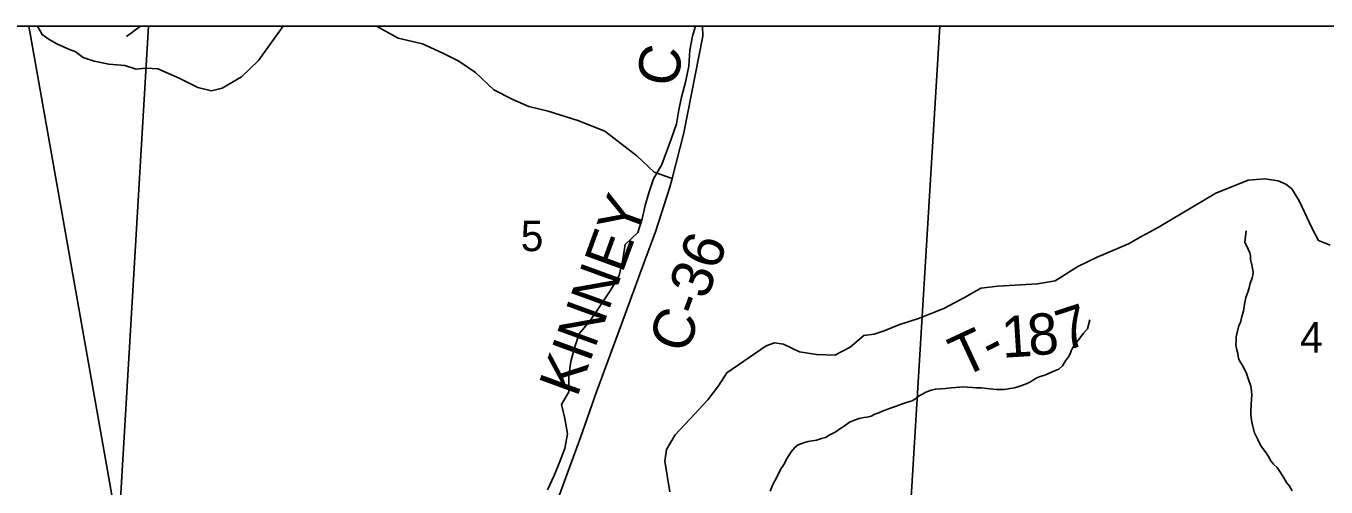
# Model space of a CAD drawing. Extents: x 0 to 34, y 0 to 22.
# Drawn here: x 3.623 to 5.409, y 20.267 to 20.9 of the extents above; entities that cross this region are included whole.
import ezdxf

# ---------------------------------------------------------------- set-up
doc = ezdxf.new("R2010")
doc.units = 0
for name, color, linetype in [('GM_X_County', 7, 'Continuous'), ('GM_X_County_Road', 7, 'Continuous'), ('GM_X_County_Road_Text', 7, 'Continuous'), ('GM_X_Minor_River', 7, 'Continuous'), ('GM_X_Section', 7, 'Continuous'), ('GM_X_Section_Text', 7, 'Continuous'), ('GM_X_Township', 7, 'Continuous'), ('GM_X_Township_Road', 7, 'Continuous'), ('GM_X_Township_Road_Text', 7, 'Continuous'), ('GM_X_Township_ROW', 7, 'Continuous'), ('SH_Data', 7, 'Continuous')]:
    doc.layers.add(name, color=color, linetype=linetype)

msp = doc.modelspace()

# ---------------------------------------------------------------- linework, layer by layer
at = {"layer": 'GM_X_County'}
msp.add_lwpolyline([(9.4175, 16.6203), (9.4175, 20.9), (2.6175, 20.9), (2.6175, 15.1694)], dxfattribs=at)
at = {"layer": 'GM_X_County_Road'}
for points in [[(4.5267, 20.7533), (4.5525, 20.8861), (4.5521, 20.9)], [(4.1667, 19.8759), (4.1807, 19.9072), (4.2007, 19.9516), (4.2252, 19.9946), (4.2509, 20.0413), (4.2643, 20.0667), (4.2739, 20.085), (4.3018, 20.1328), (4.3218, 20.1716), (4.3546, 20.2521), (4.3847, 20.3345), (4.4066, 20.3975), (4.4412, 20.4905), (4.4717, 20.5741), (4.4876, 20.6173), (4.5075, 20.6788), (4.5105, 20.6904), (4.5262, 20.7513), (4.5266, 20.7532), (4.5267, 20.7533)]]:
    msp.add_lwpolyline(points, dxfattribs=at)
at = {"layer": 'GM_X_Minor_River'}
for points in [[(3.761, 20.8854), (3.7804, 20.9)], [(4.5384, 20.8859), (4.5426, 20.9)], [(4.5384, 20.8859), (4.535, 20.8667), (4.5335, 20.8447), (4.5289, 20.8227), (4.5236, 20.8022), (4.5198, 20.7848), (4.5167, 20.7658), (4.5091, 20.7446), (4.503, 20.7271), (4.4962, 20.7097), (4.4848, 20.69), (4.4787, 20.671), (4.4734, 20.6536), (4.4696, 20.6353), (4.4635, 20.6164), (4.446, 20.5997), (4.443, 20.5792), (4.4376, 20.5572), (4.4262, 20.5375), (4.4118, 20.5155), (4.3982, 20.4958), (4.383, 20.4769), (4.3762, 20.4579), (4.3716, 20.4389), (4.3685, 20.4192), (4.3685, 20.3972), (4.3586, 20.3798), (4.3631, 20.3608), (4.3669, 20.3396), (4.3631, 20.3198), (4.3562, 20.3016), (4.3486, 20.2827), (4.3395, 20.263)], [(5.3622, 20.2615), (5.3589, 20.268), (5.3545, 20.273), (5.3508, 20.2792), (5.3464, 20.2864), (5.3416, 20.2934), (5.3367, 20.298), (5.333, 20.3026), (5.3297, 20.3084), (5.3253, 20.3156), (5.3194, 20.3233), (5.3153, 20.3318), (5.3106, 20.3413), (5.307, 20.3551), (5.3057, 20.3669), (5.3058, 20.3707), (5.306, 20.3794), (5.3065, 20.3877), (5.307, 20.393), (5.3067, 20.3987), (5.3057, 20.4052), (5.3021, 20.4159), (5.2995, 20.4228), (5.2951, 20.432), (5.2918, 20.4373), (5.2893, 20.4419), (5.2882, 20.4461), (5.2875, 20.4503), (5.2857, 20.4568), (5.2851, 20.4621), (5.2852, 20.4686), (5.2856, 20.4728), (5.2893, 20.4886), (5.2913, 20.4928), (5.2933, 20.5011), (5.2954, 20.5083), (5.297, 20.5178), (5.2987, 20.5268), (5.3015, 20.5344), (5.3031, 20.5401), (5.304, 20.545), (5.3072, 20.554), (5.3084, 20.5578), (5.3088, 20.5616), (5.3071, 20.5719), (5.3053, 20.5791), (5.305, 20.5841), (5.304, 20.5886), (5.3018, 20.5932), (5.2974, 20.6032), (5.2992, 20.6187)], [(4.8104, 20.3748), (4.8199, 20.3784), (4.8241, 20.3799), (4.8337, 20.3831), (4.8401, 20.3849), (4.8447, 20.3879), (4.8501, 20.3919), (4.8543, 20.3942), (4.8593, 20.3971), (4.8665, 20.3996), (4.8726, 20.4011), (4.8794, 20.4017), (4.8859, 20.402), (4.8942, 20.403), (4.9056, 20.4039), (4.9109, 20.4042), (4.9162, 20.4037), (4.9234, 20.4032), (4.9279, 20.4028), (4.9351, 20.4027), (4.9435, 20.4018), (4.9518, 20.4012), (4.9563, 20.4008), (4.9665, 20.4006), (4.9749, 20.402), (4.981, 20.403), (4.9855, 20.4041), (4.9894, 20.4056), (4.9985, 20.4088), (5.0027, 20.411), (5.0069, 20.414), (5.0115, 20.4166), (5.0161, 20.4184), (5.0211, 20.4198), (5.0256, 20.4217), (5.0325, 20.425), (5.0417, 20.4286), (5.0467, 20.4331), (5.0509, 20.4398), (5.0552, 20.4455), (5.0576, 20.4496), (5.0588, 20.4538), (5.0611, 20.4583), (5.0646, 20.4639), (5.0693, 20.4695), (5.0759, 20.4782), (5.0813, 20.4838), (5.0845, 20.4962)], [(4.6451, 20.261), (4.6491, 20.27), (4.6538, 20.2794), (4.6597, 20.2915), (4.6628, 20.2952), (4.6655, 20.2998), (4.6675, 20.3047), (4.6741, 20.3148), (4.6795, 20.3215), (4.6838, 20.3245), (4.6925, 20.3278), (4.6975, 20.3292), (4.7089, 20.3309), (4.7157, 20.3335), (4.7214, 20.3349), (4.7264, 20.3378), (4.731, 20.34), (4.7356, 20.3426), (4.741, 20.3467), (4.7467, 20.3504), (4.7544, 20.3556), (4.7609, 20.3585), (4.7673, 20.3607), (4.7738, 20.3621), (4.7787, 20.3628), (4.7841, 20.3642), (4.789, 20.3668), (4.7944, 20.3686), (4.8005, 20.3715), (4.8104, 20.3748)]]:
    msp.add_lwpolyline(points, dxfattribs=at)
at = {"layer": 'GM_X_Section'}
for p, q in [((3.7913, 20.9), (2.7184, 20.9)), ((4.8782, 20.9), (3.7913, 20.9)), ((5.9593, 20.9), (4.8782, 20.9))]:
    msp.add_line(p, q, dxfattribs=at)
for points in [[(2.7184, 20.9), (2.6713, 20.205), (3.7462, 20.1418), (3.7913, 20.9)], [(3.7913, 20.9), (3.7462, 20.1418), (4.8284, 20.0797), (4.8782, 20.9)], [(4.8782, 20.9), (4.8284, 20.0797), (5.9068, 20.018), (5.9593, 20.9)]]:
    msp.add_lwpolyline(points, dxfattribs=at)
at = {"layer": 'GM_X_Township'}
msp.add_line((8.2133, 20.9), (2.7154, 20.9), dxfattribs=at)
at = {"layer": 'GM_X_Township_Road'}
for points in [[(3.6578, 20.7243), (3.6267, 20.9)], [(3.6388, 20.9), (3.645, 20.8882), (3.6545, 20.8814), (3.6651, 20.8753), (3.6834, 20.8674), (3.6906, 20.8648), (3.7016, 20.8568), (3.7167, 20.8516), (3.7365, 20.8474), (3.7588, 20.8456), (3.7744, 20.8407), (3.7869, 20.8422), (3.7964, 20.8415), (3.804, 20.8411), (3.8332, 20.8283), (3.859, 20.8155), (3.8776, 20.811), (3.8923, 20.8148), (3.9188, 20.83), (3.9423, 20.8525), (3.9642, 20.8832), (3.9763, 20.9)], [(4.1046, 20.9), (4.1342, 20.8832), (4.1674, 20.8753), (4.1955, 20.8625), (4.2175, 20.8516), (4.2406, 20.8361), (4.2657, 20.8122), (4.2915, 20.799), (4.3135, 20.7892), (4.3401, 20.7832), (4.381, 20.7704), (4.4179, 20.7556), (4.4619, 20.7216), (4.4858, 20.6993), (4.5105, 20.6904)], [(5.1609, 20.6138), (5.1611, 20.6139), (5.1797, 20.6239), (5.2577, 20.6704), (5.3017, 20.688), (5.3248, 20.69), (5.343, 20.6874), (5.3536, 20.6828), (5.362, 20.6764), (5.3722, 20.6597), (5.3898, 20.6218), (5.3985, 20.6052), (5.4145, 20.5988)], [(4.5074, 20.26), (4.5004, 20.3021), (4.503, 20.3184), (4.5147, 20.3382), (4.5412, 20.3667), (4.5594, 20.3865), (4.5741, 20.4058), (4.5858, 20.4237), (4.6399, 20.4606), (4.6513, 20.4648), (4.6634, 20.463), (4.6854, 20.4524), (4.7089, 20.4487), (4.734, 20.448), (4.7552, 20.459), (4.7741, 20.4746), (4.7881, 20.4765), (4.8017, 20.4811), (4.8222, 20.4895), (4.8491, 20.4983), (4.8836, 20.512), (4.9131, 20.5273), (4.9347, 20.5399), (4.9578, 20.5426), (5.0127, 20.5457), (5.0366, 20.55), (5.0677, 20.5694), (5.0945, 20.5824), (5.1184, 20.5923), (5.1377, 20.6007), (5.1544, 20.6102), (5.1609, 20.6138)], [(3.6963, 19.9816), (3.7173, 19.9957), (3.7328, 20.0075), (3.7392, 20.0223), (3.7425, 20.0618), (3.7409, 20.1107), (3.7454, 20.1449), (3.7505, 20.2006), (3.7375, 20.274)]]:
    msp.add_lwpolyline(points, dxfattribs=at)
at = {"layer": 'GM_X_Township_ROW'}
msp.add_lwpolyline([(3.7375, 20.274), (3.6578, 20.7243)], dxfattribs=at)
at = {"layer": 'SH_Data'}
msp.add_line((2.6, 20.9), (9.4, 20.9), dxfattribs=at)

# ---------------------------------------------------------------- texts
at = {"layer": 'GM_X_County_Road_Text'}
for s, height, rotation, p in [('C', 0.0568, 79.4691, (4.5163, 20.8142)), ('KINNEY', 0.05682, 69.9561, (4.3798, 20.3886)), ('C-36', 0.05682, 69.7236, (4.5301, 20.4476))]:
    msp.add_text(s, height=height, rotation=rotation, dxfattribs=at).set_placement(p)
at = {"layer": 'GM_X_Section_Text'}
for s, p in [('5', (4.3025, 20.5907)), ('4', (5.3733, 20.4513))]:
    msp.add_text(s, height=0.0419, rotation=0, dxfattribs=at).set_placement(p)
at = {"layer": 'GM_X_Township_Road_Text'}
for s, rotation, p in [('8', 5.7859, (5.0017, 20.4465)), ('7', 18.0099, (5.0495, 20.4528)), ('T', 24.977, (4.909, 20.4163)), ('1', 3.588, (4.9644, 20.4441)), ('-', 27.0117, (4.9495, 20.4352))]:
    msp.add_text(s, height=0.0568, rotation=rotation, dxfattribs=at).set_placement(p)

doc.saveas('drawing.dxf')
